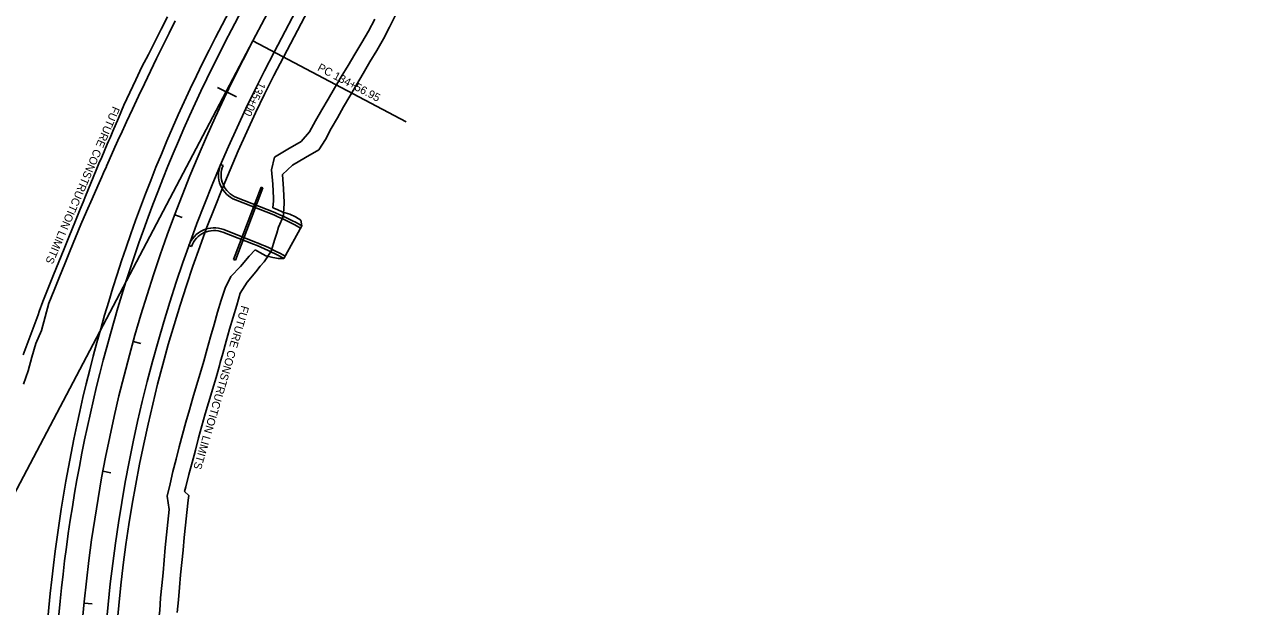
# Model space of a CAD drawing. Extents: x 979959 to 994833, y 1835619 to 1845316.
# Drawn here: x 980546 to 981473, y 1839689 to 1840125 of the extents above; entities that cross this region are included whole.
import ezdxf

# ---------------------------------------------------------------- set-up
doc = ezdxf.new("R2010")
doc.units = 0
for name, color, linetype in [('Future 5 Lane Construction Limits', 7, 'Continuous'), ('R_Drainage', 7, 'Continuous'), ('R_Horz Alg', 7, 'Continuous'), ('R_Horz Alg Annot', 7, 'Continuous'), ('R_Horz Alg Annot_Side Road', 7, 'Continuous'), ('R_Horz Alg Stationing', 7, 'Continuous'), ('R_Proposed Const Limits', 7, 'Continuous'), ('R_Proposed Road', 7, 'Continuous')]:
    doc.layers.add(name, color=color, linetype=linetype)

msp = doc.modelspace()

# ---------------------------------------------------------------- linework, layer by layer
at = {"layer": 'Future 5 Lane Construction Limits'}
for points in [[(980545.21, 1839877.63), (980548.79, 1839887.72), (980552.55, 1839897.75), (980556.25, 1839907.78), (980557.19, 1839910.26), (980559.97, 1839917.79), (980563.75, 1839927.76), (980567.82, 1839937.63), (980571.92, 1839947.48), (980575.94, 1839957.33), (980579.93, 1839967.18), (980583.89, 1839977.03), (980587.83, 1839986.87), (980590.04, 1839992.32), (980591.78, 1839996.71), (980595.81, 1840006.5), (980599.9, 1840016.27), (980601.96, 1840021.15), (980604.02, 1840026.02), (980608.19, 1840035.75), (980609.14, 1840037.97), (980610.23, 1840040.49), (980612.4, 1840045.46), (980616.65, 1840055.15), (980620.64, 1840064.94), (980625.06, 1840074.55), (980629.62, 1840084.1), (980634.13, 1840093.66), (980639.03, 1840103.04), (980643.74, 1840112.5), (980648.53, 1840121.92), (980653.39, 1840131.31)], [(980824.38, 1840132.48), (980819.86, 1840123.56), (980815.27, 1840114.68), (980810.22, 1840106.04), (980805.15, 1840097.4), (980800.05, 1840088.79), (980795.01, 1840080.14), (980790, 1840071.73), (980785.36, 1840063.69), (980780.79, 1840055.61), (980776.19, 1840047.53), (980771.77, 1840039.35), (980766.75, 1840031.45), (980756.93, 1840025.73), (980747.09, 1840019.89), (980739.65, 1840012.87), (980740.32, 1840002.32), (980740.9, 1839991.89), (980740.57, 1839986.84), (980740.42, 1839984.28), (980740.28, 1839982.03), (980736.67, 1839973.43), (980735.41, 1839968.9), (980733.91, 1839964.48), (980731.17, 1839955.54), (980725.79, 1839947.59), (980722.91, 1839944.21), (980719.47, 1839939.92), (980712.99, 1839932.25), (980707.8, 1839924.07), (980705.25, 1839914.99), (980702.51, 1839905.98), (980699.84, 1839896.94), (980697.25, 1839887.89), (980694.73, 1839878.82), (980692.88, 1839871.99), (980692.28, 1839869.73), (980689.73, 1839860.66), (980686.96, 1839851.65), (980684.26, 1839842.62), (980684.02, 1839841.78), (980681.64, 1839833.57), (980679.09, 1839824.48), (980676.61, 1839815.38), (980674.21, 1839806.25), (980673.22, 1839802.53), (980671.76, 1839797.12), (980669.34, 1839787.98), (980666.98, 1839778.81), (980666.09, 1839775.28), (980669.33, 1839772.31), (980668.91, 1839768.87), (980667.83, 1839759.5), (980666.85, 1839750.13), (980665.96, 1839740.74), (980665.14, 1839731.37), (980664.09, 1839722.03), (980663.13, 1839712.68), (980662.36, 1839703.31), (980661.5, 1839693.96), (980660.64, 1839684.61)]]:
    msp.add_lwpolyline(points, dxfattribs=at)
at = {"layer": 'R_Drainage'}
for p, q in [((980723.55, 1840003.41), (980702.83, 1839949.23)), ((980724.95, 1840002.87), (980704.24, 1839948.7)), ((980723.55, 1840003.41), (980724.95, 1840002.87)), ((980702.83, 1839949.23), (980704.24, 1839948.7))]:
    msp.add_line(p, q, dxfattribs=at)
at = {"layer": 'R_Horz Alg'}
msp.add_line((981456.9, 1841516.96), (980717.33, 1840113.21), dxfattribs=at)
msp.add_arc((981731.15, 1839579.08), 1145.92, 152.21752, 253.16792, dxfattribs=at)
at = {"layer": 'R_Horz Alg Annot'}
msp.add_lwpolyline([(980717.33, 1840113.21), (980832.34, 1840052.61)], dxfattribs=at)
at = {"layer": 'R_Horz Alg Annot_Side Road'}
msp.add_line((980717.33, 1840113.21), (980069.95, 1838884.43), dxfattribs=at)
at = {"layer": 'R_Horz Alg Stationing'}
for points in [[(980705.2, 1840071.29), (980690.77, 1840078.22)], [(980664.33, 1839980.71), (980658.72, 1839982.82)], [(980633.39, 1839886.2), (980627.61, 1839887.82)], [(980610.8, 1839789.36), (980604.9, 1839790.46)], [(980596.73, 1839690.91), (980590.76, 1839691.5)]]:
    msp.add_lwpolyline(points, dxfattribs=at)
at = {"layer": 'R_Proposed Const Limits'}
msp.add_line((980753.26, 1839978.71), (980754.03, 1839974.58), dxfattribs=at)
for points in [[(980545.42, 1839855.66), (980548.77, 1839865.78), (980551.56, 1839876.03), (980554.48, 1839886.24), (980558.75, 1839896.08), (980561.69, 1839906.26), (980564.38, 1839916.51), (980568.43, 1839926.37), (980572.34, 1839936.24), (980576.29, 1839946.09), (980580.29, 1839955.91), (980584.33, 1839965.7), (980588.4, 1839975.46), (980592.62, 1839985.16), (980596.82, 1839994.86), (980601.08, 1840004.52), (980603.99, 1840011.14), (980605.34, 1840014.17), (980607.48, 1840018.99), (980607.5, 1840019.04), (980607.56, 1840019.18), (980609.6, 1840023.81), (980613.93, 1840033.42), (980617.46, 1840041.13), (980618.29, 1840043), (980622.64, 1840052.59), (980627.12, 1840062.11), (980631.61, 1840071.62), (980636.17, 1840081.09), (980640.68, 1840090.59), (980645.21, 1840100.07), (980649.83, 1840109.51), (980654.5, 1840118.93), (980659.21, 1840128.33)], [(980808.76, 1840129.41), (980804.17, 1840120.53), (980799.1, 1840111.89), (980793.89, 1840103.33), (980788.78, 1840094.72), (980783.64, 1840086.13), (980778.57, 1840077.71), (980773.85, 1840069.59), (980769.04, 1840061.5), (980764.37, 1840053.33), (980759.78, 1840045.11), (980753.45, 1840037.69), (980743.53, 1840031.87), (980733.57, 1840025.94)], [(980733.57, 1840025.94), (980731.35, 1840016.5), (980732.29, 1840005.75), (980732.94, 1839995.21), (980732.82, 1839993.26), (980732.22, 1839988.02)], [(980732.22, 1839988.02), (980735.63, 1839986.72), (980739.92, 1839984.77)], [(980739.92, 1839984.77), (980745.01, 1839983.16), (980749.29, 1839981.24), (980753.26, 1839978.71)], [(980719.02, 1839956.41), (980714.6, 1839951.69), (980707.99, 1839944.01), (980700.74, 1839936.5), (980696.52, 1839927.87)], [(980719.02, 1839956.41), (980722.67, 1839954.43), (980727.1, 1839952.03), (980732.45, 1839950.79), (980736.49, 1839949.96), (980740.6, 1839950.02)], [(980653.05, 1839771.7), (980655.23, 1839781.02), (980657.43, 1839790.32), (980659.83, 1839799.57), (980662.2, 1839808.83), (980664.65, 1839818.06), (980667.16, 1839827.27), (980669.74, 1839836.45), (980672.41, 1839845.61), (980675.13, 1839854.74), (980677.95, 1839863.85), (980680.58, 1839873), (980683.06, 1839882.19), (980685.6, 1839891.37), (980688.23, 1839900.52), (980690.92, 1839909.66), (980693.68, 1839918.78), (980696.52, 1839927.87)], [(980653.05, 1839771.7), (980654.57, 1839761.75), (980653.57, 1839752.26), (980652.65, 1839742.76), (980651.66, 1839733.29), (980650.73, 1839723.81), (980650.02, 1839714.32), (980649.08, 1839704.85), (980648.2, 1839695.39), (980647.5, 1839685.91), (980646.41, 1839676.46), (980645.42, 1839667.01), (980644.55, 1839657.54), (980643.78, 1839648.06), (980643.1, 1839638.58), (980643.02, 1839637.12), (980642.61, 1839629.08), (980641.32, 1839619.83)]]:
    msp.add_lwpolyline(points, dxfattribs=at)
at = {"layer": 'R_Proposed Road'}
for p, q in [((981440.97, 1841525.35), (980701.4, 1840121.6)), ((981472.82, 1841508.57), (980733.25, 1840104.82)), ((981337, 1841345.16), (980694.33, 1840125.33)), ((981371.29, 1841298.7), (980740.33, 1840101.09)), ((980695.01, 1840019.64), (980693.17, 1840020.43)), ((980727.33, 1839984.95), (980704.28, 1839993.98)), ((980728.06, 1839986.82), (980705.01, 1839995.84)), ((980717.85, 1839960.74), (980694.8, 1839969.77)), ((980718.58, 1839962.61), (980695.53, 1839971.63)), ((980754.03, 1839974.58), (980740.6, 1839950.02)), ((980753.07, 1839972.83), (980751.76, 1839973.55)), ((980754.03, 1839974.58), (980752.72, 1839975.3)), ((980671.3, 1839959.08), (980669.41, 1839959.75)), ((980740.6, 1839950.02), (980739.29, 1839950.74)), ((980741.56, 1839951.77), (980740.25, 1839952.49))]:
    msp.add_line(p, q, dxfattribs=at)
for centre, radius, start, end in [((981731.15, 1839579.08), 1171.92, 152.21752, 185.64733), ((981731.15, 1839579.08), 1163.92, 152.21752, 184.48963), ((981731.15, 1839579.08), 1127.92, 152.21752, 253.16792), ((981731.15, 1839579.08), 1119.92, 152.21752, 253.16792), ((980711.57, 1840012.6), 20, 156.96485, 248.61996), ((980711.57, 1840012.6), 18, 156.96485, 248.61996), ((980650.04, 1839787.54), 212, 61.32761, 68.61996), ((980650.04, 1839787.54), 214, 61.32761, 68.61996), ((980688.24, 1839953), 20, 68.61996, 160.27507), ((980688.24, 1839953), 18, 68.61996, 160.27507), ((980650.04, 1839787.54), 186, 61.32761, 68.61996), ((980650.04, 1839787.54), 188, 61.32761, 68.61996)]:
    msp.add_arc(centre, radius, start, end, dxfattribs=at)

# ---------------------------------------------------------------- texts
at = {"layer": 'Future 5 Lane Construction Limits'}
for rotation, p in [(246.60455, (980612.3, 1840064.61)), (253.51236, (980708.83, 1839915.12))]:
    msp.add_text('FUTURE CONSTRUCTION LIMITS', height=6, rotation=rotation, dxfattribs=at).set_placement(p)
at = {"layer": 'R_Horz Alg Annot'}
msp.add_text('PC 134+56.95', height=6, rotation=332.21752, dxfattribs=at).set_placement((980765.29, 1840091.33))
at = {"layer": 'R_Horz Alg Stationing'}
msp.add_text('135+00', height=6, rotation=244.36988, dxfattribs=at).set_placement((980721.85, 1840082.88))

doc.saveas('drawing.dxf')
